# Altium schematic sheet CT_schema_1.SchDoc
size 442 x 402 mm
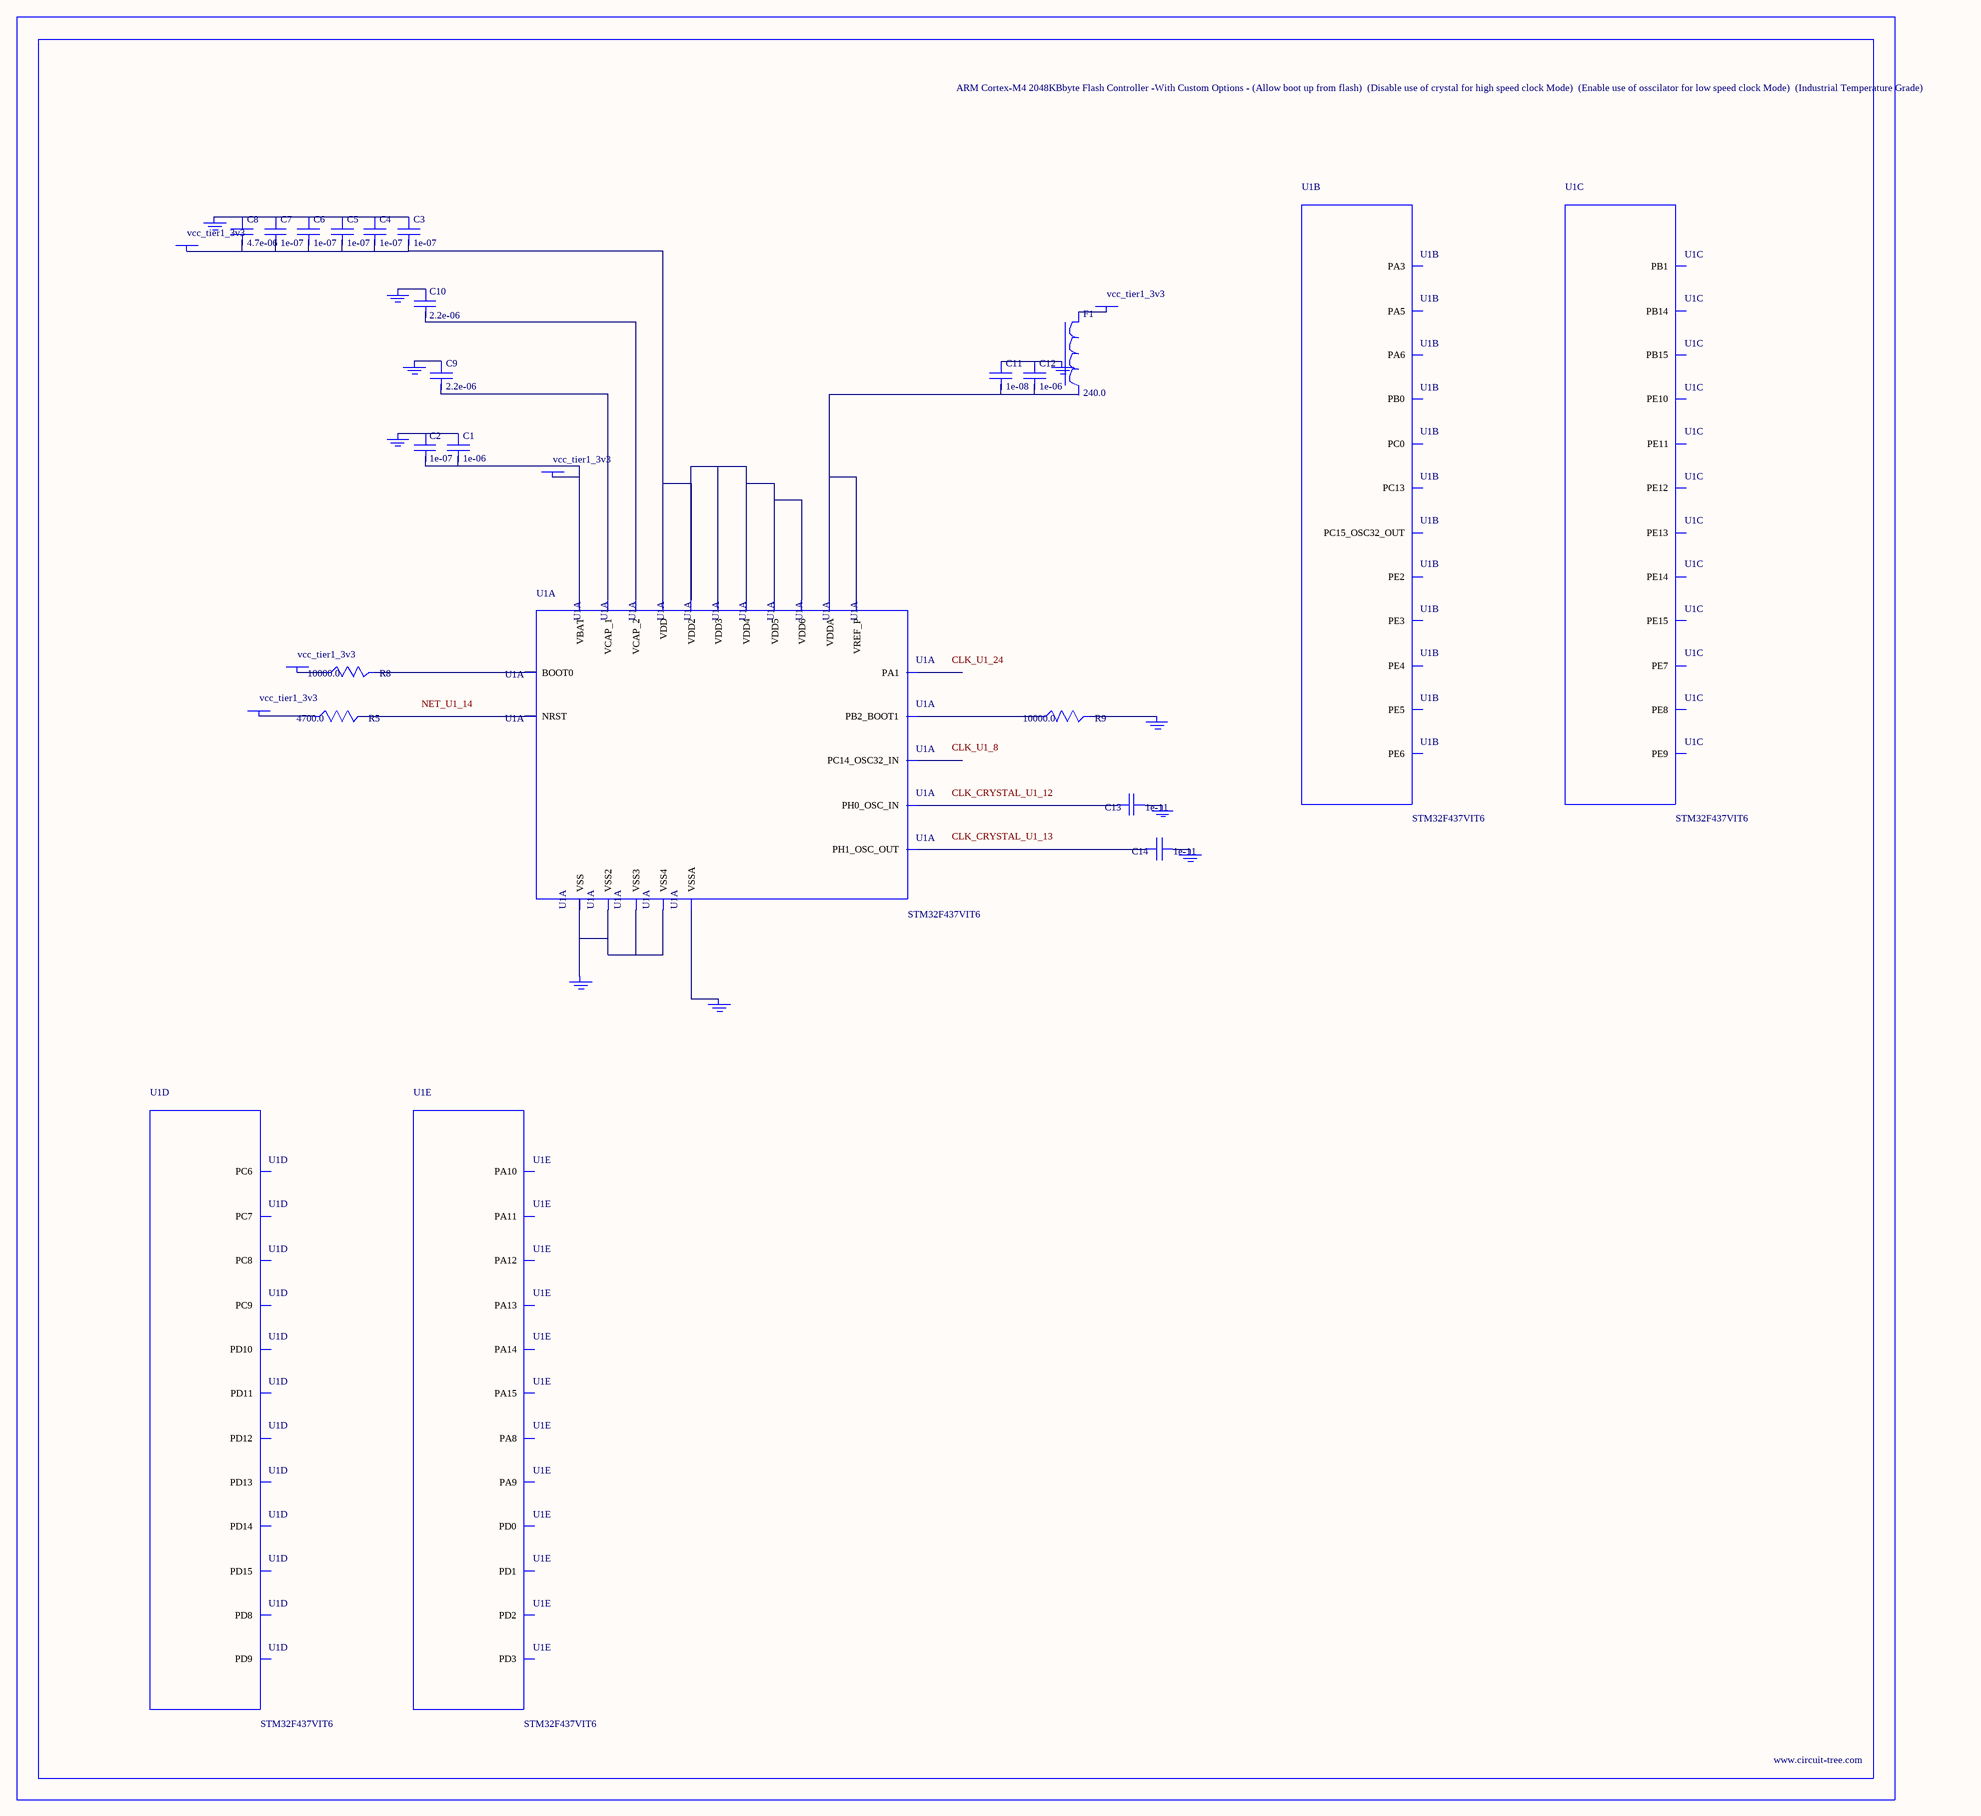
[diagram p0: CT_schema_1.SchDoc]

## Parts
BORDER0  (no value)
C1  1e-06  [C0603]
C2  1e-07  [C0603]
C3  1e-07  [C0603]
C4  1e-07  [C0603]
C5  1e-07  [C0603]
C6  1e-07  [C0603]
C7  1e-07  [C0603]
C8  4.7e-06  [C0603]
C9  2.2e-06  [C0603]
C10  2.2e-06  [C0603]
C11  1e-08  [C0603]
C12  1e-06  [C0603]
C13  1e-11  [C0402]
C14  1e-11  [C0402]
F1  240.0  [L0603]
GND_INSTANCE_0_0  (no value)
GND_INSTANCE_0_1  (no value)
GND_INSTANCE_0_2  (no value)
GND_INSTANCE_0_3  (no value)
GND_INSTANCE_0_4  (no value)
GND_INSTANCE_0_5  (no value)
GND_INSTANCE_0_6  (no value)
GND_INSTANCE_0_7  (no value)
GND_INSTANCE_0_8  (no value)
GND_INSTANCE_0_9  (no value)
POWER_INSTANCE_0_0  vcc_tier1_3v3
POWER_INSTANCE_0_1  vcc_tier1_3v3
POWER_INSTANCE_0_2  vcc_tier1_3v3
POWER_INSTANCE_0_3  vcc_tier1_3v3
POWER_INSTANCE_0_4  vcc_tier1_3v3
R5  4700.0  [R0603]
R8  10000.0  [R0603]
R9  10000.0  [R0603]
U1  STM32F437VIT6  [LQFP100]  (parts A,B,C,D,E of 9)

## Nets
NetC1_1: C1.1 C2.1 GND_INSTANCE_0_0.0(GND)
NetC1_2: C1.2 C2.2 POWER_INSTANCE_0_0.0(PWR) U1.6(VBAT)
NetC3_1: C3.1 C4.1 C5.1 C6.1 C7.1 C8.1 GND_INSTANCE_0_1.0(GND)
NetC3_2: C3.2 C4.2 C5.2 C6.2 C7.2 C8.2 POWER_INSTANCE_0_1.0(PWR) U1.11(VDD) U1.19(VDD2) U1.28(VDD3) U1.50(VDD4) U1.75(VDD5) U1.100(VDD6)
NetC9_1: C9.1 GND_INSTANCE_0_7.0(GND)
NetC9_2: C9.2 U1.49(VCAP_1)
NetC10_1: C10.1 GND_INSTANCE_0_8.0(GND)
NetC10_2: C10.2 U1.73(VCAP_2)
NetC11_1: C11.1 C12.1 GND_INSTANCE_0_5.0(GND)
NetC11_2: C11.2 C12.2 U1.21(VREF_P) U1.22(VDDA)
NetC13_1: C13.1 GND_INSTANCE_0_2.0(GND)
NetC13_2: C13.2 U1.12(PH0_OSC_IN)
NetC14_1: C14.1 GND_INSTANCE_0_3.0(GND)
NetC14_2: C14.2 U1.13(PH1_OSC_OUT)
NetF1_1: F1.1 POWER_INSTANCE_0_2.0(PWR)
NetGND_INSTANCE_0_4_0: GND_INSTANCE_0_4.0(GND) U1.20(VSSA)
NetGND_INSTANCE_0_6_0: GND_INSTANCE_0_6.0(GND) R9.2
NetGND_INSTANCE_0_9_0: GND_INSTANCE_0_9.0(GND) U1.10(VSS) U1.27(VSS2) U1.74(VSS3) U1.99(VSS4)
NetPOWER_INSTANCE_0_3_0: POWER_INSTANCE_0_3.0(PWR) R8.1
NetPOWER_INSTANCE_0_4_0: POWER_INSTANCE_0_4.0(PWR) R5.1
NetR5_2: R5.2 U1.14(NRST)
NetR8_2: R8.2 U1.94(BOOT0)
NetR9_1: R9.1 U1.37(PB2_BOOT1)

Not connected (* = marked no-connect by the designer): F1 2; U1 1(PE2) 2(PE3) 3(PE4) 4(PE5) 5(PE6) 7(PC13) 8(PC14_OSC32_IN) 9(PC15_OSC32_OUT) 15(PC0) 24(PA1) 26(PA3) 30(PA5) 31(PA6) 35(PB0) 36(PB1) 38(PE7) 39(PE8) 40(PE9) 41(PE10) 42(PE11) 43(PE12) 44(PE13) 45(PE14) 46(PE15) 53(PB14) 54(PB15) 55(PD8) 56(PD9) 57(PD10) 58(PD11) 59(PD12) 60(PD13) 61(PD14) 62(PD15) 63(PC6) 64(PC7) 65(PC8) 66(PC9) 67(PA8) 68(PA9) 69(PA10) 70(PA11) 71(PA12) 72(PA13) 76(PA14) 77(PA15) 81(PD0) 82(PD1) 83(PD2) 84(PD3)

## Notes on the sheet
- Labels drawn without touching a wire or pin: CLK_CRYSTAL_U1_12, CLK_CRYSTAL_U1_13, CLK_U1_8, CLK_U1_24, NET_U1_14

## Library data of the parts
BORDER0 = BORDER_PAGE0
C1 C12 = C0603C105K3RACTU
C2-C7 = 06035C104K4Z2A
C8 = GRM188R6YA475KE15D
C9 C10 = C0603C225K8RACTU
C11 = 06035C103K4Z2A
C13 C14 = C0402C100K3GACTU
F1 = Z0603C241ASMST
GND_INSTANCE_0_0-GND_INSTANCE_0_9 = GND
POWER_INSTANCE_0_0-POWER_INSTANCE_0_4 = PWR
R5 = RC0603JR-074K7L
R8 R9 = RC0603JR-0710KL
